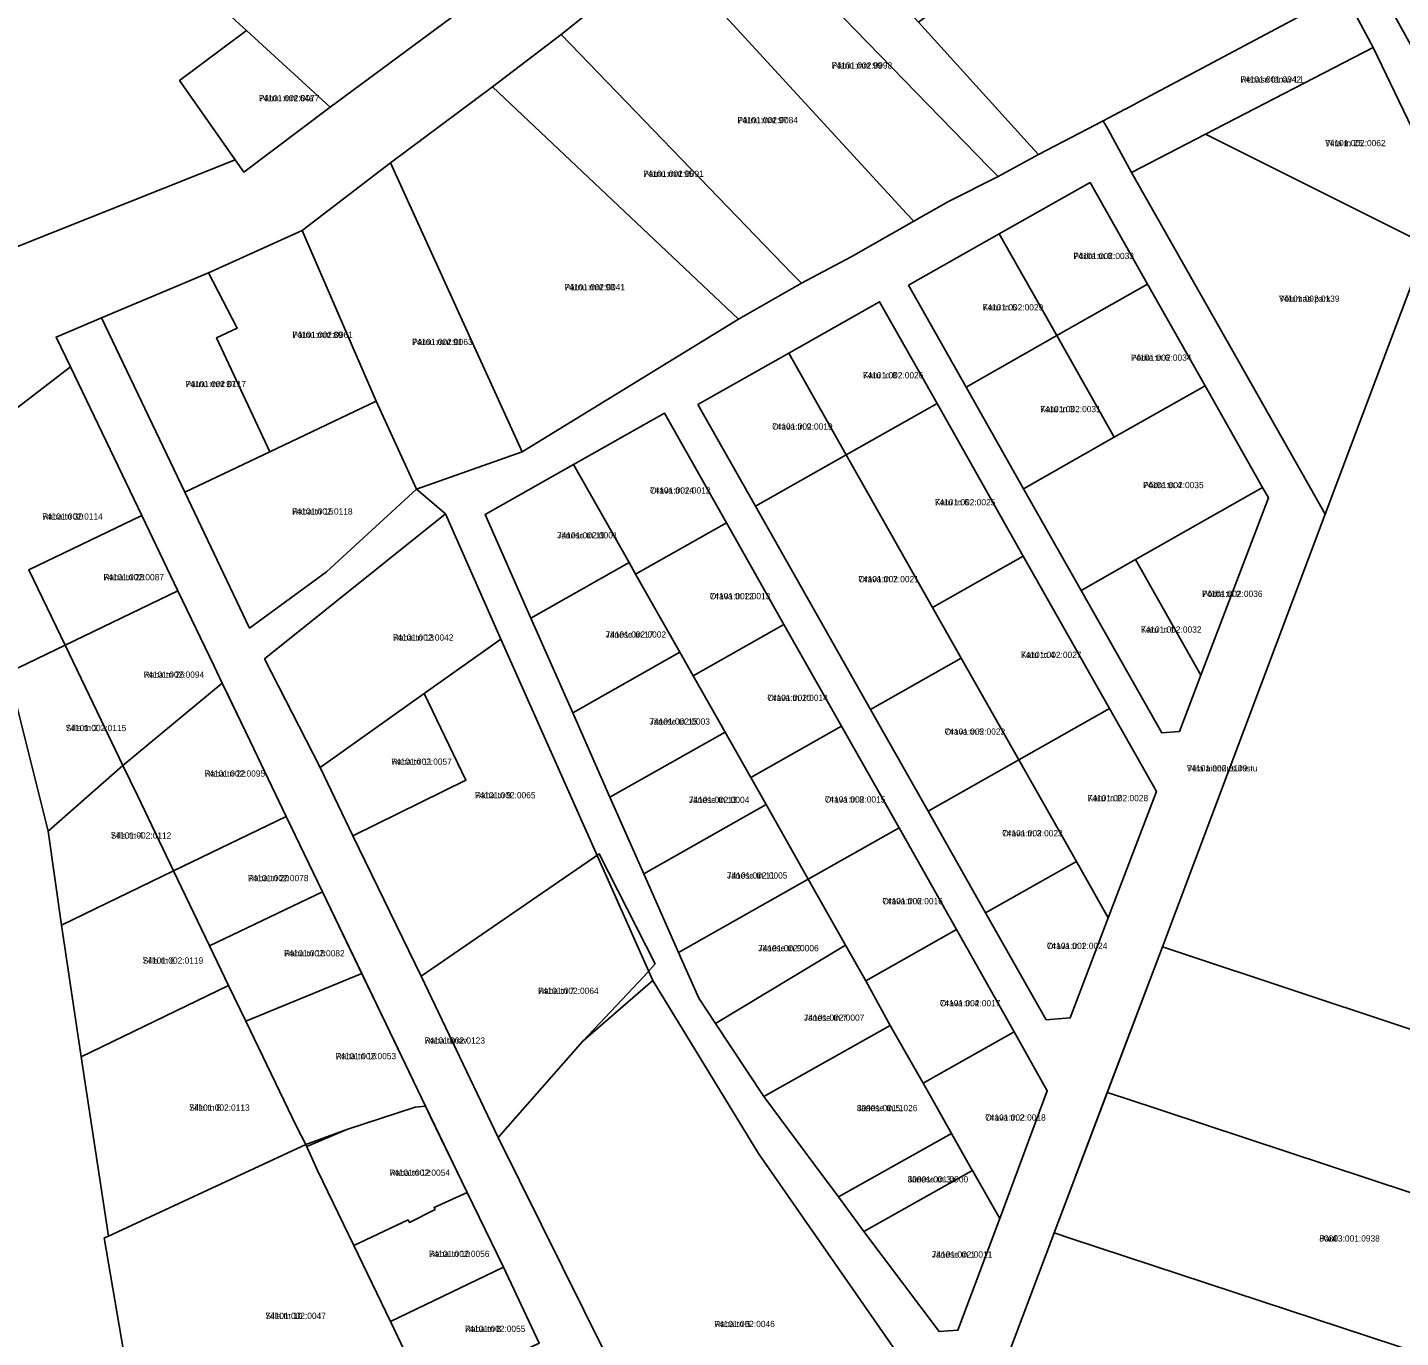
# Model space of a CAD drawing. Extents: x 524000 to 564260, y 6469338 to 6496391.
# Drawn here: x 539303.8 to 539632.9, y 6474807.9 to 6475121.9 of the extents above; entities that cross this region are included whole.
import ezdxf

# ---------------------------------------------------------------- set-up
doc = ezdxf.new("R2010")
doc.units = 0
for name, color, linetype in [('L_AADRESS', 7, 'Continuous'), ('PIIR', 7, 'Continuous'), ('TUNNUS', 7, 'Continuous')]:
    doc.layers.add(name, color=color, linetype=linetype)

msp = doc.modelspace()

# ---------------------------------------------------------------- linework, layer by layer
at = {"layer": 'PIIR'}
for points in [[(539295.23, 6475337.55), (539350.69, 6475352.27), (539371.64, 6475348.56), (539404.12, 6475358.99), (539449.99, 6475367.58), (539454.72, 6475343.6), (539447.84, 6475341.41), (539440.94, 6475342.71), (539417.67, 6475333.57), (539446.06, 6475253.45), (539454.39, 6475235.4), (539416.27, 6475208.15), (539414.96, 6475204.32), (539400.63, 6475162.15), (539381.45, 6475172.98), (539379.48, 6475174.52), (539352.83, 6475124.35), (539356.29, 6475121.18), (539340.27, 6475109.17), (539353.64, 6475090.16), (539301.46, 6475069.45)], [(539456.7, 6475140.24), (539431.73, 6475120.22), (539415.28, 6475107.69), (539390.84, 6475089.49), (539369.67, 6475073.29), (539347.22, 6475063.12), (539321.55, 6475052.32), (539310.68, 6475047.72), (539314.11, 6475040.57), (539281.27, 6475015.31)], [(539301.46, 6475069.45), (539353.64, 6475090.16), (539355.68, 6475087.26), (539376.38, 6475102.78), (539412.45, 6475129.6)], [(539426.49, 6474806.62), (539417.93, 6474824.8), (539409.17, 6474842.68), (539399.21, 6474863.41), (539395.31, 6474871.52), (539391.85, 6474878.73), (539383.19, 6474896.76), (539374.53, 6474914.79), (539365.87, 6474932.81), (539357.21, 6474950.83), (539351.15, 6474963.45), (539350.5, 6474964.8), (539348.55, 6474968.86), (539339.89, 6474986.89), (539331.23, 6475004.92), (539314.11, 6475040.57), (539310.68, 6475047.72), (539321.55, 6475052.32), (539341.52, 6475010.53), (539357.08, 6474977.98), (539375.46, 6474991.41), (539397.03, 6475011.25), (539403.99, 6475005.38), (539360.64, 6474970.59), (539373.97, 6474944.52), (539381.83, 6474928.14), (539398.18, 6474894.53), (539416.64, 6474855.92), (539473.23, 6474741.88)]]:
    msp.add_lwpolyline(points, dxfattribs=at)
for points in [[(539605.37, 6475156.48), (539549.38, 6475215.78), (539554.03, 6475218.82), (539561.15, 6475210.35), (539597.66, 6475177.19), (539603.22, 6475172.2), (539612.5, 6475163.41), (539621.61, 6475144.62), (539625.52, 6475135.5), (539642.98, 6475104.01), (539647.08, 6475099.52), (539649.32, 6475097.06), (539649.25, 6475096.88), (539643.46, 6475081.48), (539641.9, 6475084.73), (539626.35, 6475117.08), (539619.33, 6475130.28)], [(539411.99, 6475130.54), (539412.45, 6475129.6), (539376.38, 6475102.78), (539356.29, 6475121.18), (539352.83, 6475124.35), (539379.48, 6475174.52), (539381.45, 6475172.98), (539400.63, 6475162.15), (539403.34, 6475160.78)], [(539546.15, 6475091.47), (539544.25, 6475093.57), (539517.4, 6475123.15), (539538.81, 6475138.94), (539539.57, 6475139.5), (539534.11, 6475145.91), (539565.08, 6475172.46), (539591.7, 6475144.75), (539605.37, 6475156.48), (539619.33, 6475130.28), (539571.71, 6475104.85), (539566.99, 6475102.33), (539566.92, 6475102.34), (539561.62, 6475099.53)], [(539474.41, 6475135.12), (539464.3, 6475146.34), (539462.39, 6475148.47), (539481.3, 6475162.97), (539517.4, 6475123.15), (539544.25, 6475093.57), (539546.15, 6475091.47), (539536.43, 6475086.16), (539534.11, 6475088.54), (539482.15, 6475142.07)], [(539514.52, 6475077.34), (539456.7, 6475140.24), (539464.3, 6475146.34), (539474.41, 6475135.12), (539482.15, 6475142.07), (539534.11, 6475088.54), (539536.43, 6475086.16), (539524.57, 6475080.22), (539516.23, 6475075.48)], [(539456.7, 6475140.24), (539514.52, 6475077.34), (539516.23, 6475075.48), (539501.22, 6475066.95), (539489.3, 6475060.62), (539487.12, 6475062.89), (539431.73, 6475120.22)], [(539566.99, 6475102.33), (539571.71, 6475104.85), (539619.33, 6475130.28), (539626.35, 6475117.08), (539586.17, 6475096.34), (539568.44, 6475087.13), (539562.88, 6475097.3), (539561.62, 6475099.53), (539566.92, 6475102.34)], [(539355.68, 6475087.26), (539340.27, 6475109.17), (539356.29, 6475121.18), (539376.38, 6475102.78)], [(539474.22, 6475052), (539415.28, 6475107.69), (539431.73, 6475120.22), (539487.12, 6475062.89), (539489.3, 6475060.62)], [(539586.17, 6475096.34), (539626.35, 6475117.08), (539641.9, 6475084.73), (539643.46, 6475081.48), (539639.08, 6475069.84), (539637.08, 6475070.84)], [(539422.37, 6475020.22), (539390.84, 6475089.49), (539415.28, 6475107.69), (539474.22, 6475052)], [(539546.15, 6475091.47), (539561.62, 6475099.53), (539562.88, 6475097.3), (539568.44, 6475087.13), (539610.58, 6475012.76), (539614.81, 6475005.29), (539575.81, 6474901.59), (539549.89, 6474833.01), (539549.8, 6474832.79), (539532.8, 6474787.68), (539526.92, 6474790.08), (539520.24, 6474792.81), (539479.01, 6474852.03), (539453.69, 6474893.5), (539417.25, 6474975.31), (539403.99, 6475005.38), (539397.03, 6475011.25), (539422.37, 6475020.22), (539474.22, 6475052), (539489.3, 6475060.62), (539501.22, 6475066.95), (539516.23, 6475075.48), (539524.57, 6475080.22), (539536.43, 6475086.16)], [(539568.44, 6475087.13), (539586.17, 6475096.34), (539637.08, 6475070.84), (539639.08, 6475069.84), (539614.81, 6475005.29), (539610.58, 6475012.76)], [(539649.25, 6475096.88), (539656.29, 6475089.89), (539687.76, 6475058.65), (539763.32, 6474839.28), (539580.15, 6474900.15), (539575.81, 6474901.59), (539614.81, 6475005.29), (539639.08, 6475069.84), (539643.46, 6475081.48)], [(539387.43, 6475032.37), (539369.67, 6475073.29), (539390.84, 6475089.49), (539422.37, 6475020.22), (539397.03, 6475011.25)], [(539558.49, 6475084.74), (539536.73, 6475072.43), (539514.99, 6475060.11), (539528.77, 6475035.74), (539542.55, 6475011.37), (539556.34, 6474987), (539575.67, 6474952.84), (539579.88, 6474953.21), (539585.04, 6474966.72), (539601.25, 6475009.16), (539599.85, 6475011.63), (539586.06, 6475036), (539572.27, 6475060.37)], [(539536.73, 6475072.43), (539558.49, 6475084.74), (539572.27, 6475060.37), (539550.52, 6475048.06)], [(539354.06, 6475049.84), (539347.22, 6475063.12), (539369.67, 6475073.29), (539387.43, 6475032.37), (539361.88, 6475020.21), (539349.16, 6475047.56)], [(539514.99, 6475060.11), (539536.73, 6475072.43), (539550.52, 6475048.06), (539528.77, 6475035.74)], [(539321.55, 6475052.32), (539347.22, 6475063.12), (539354.06, 6475049.84), (539349.16, 6475047.56), (539361.88, 6475020.21), (539341.52, 6475010.53)], [(539572.27, 6475060.37), (539586.06, 6475036), (539564.3, 6475023.69), (539550.52, 6475048.06)], [(539508.03, 6475056.17), (539486.27, 6475043.85), (539464.51, 6475031.54), (539478.3, 6475007.17), (539505.87, 6474958.43), (539519.66, 6474934.06), (539533.45, 6474909.69), (539547.93, 6474884.1), (539553.68, 6474884.53), (539562.83, 6474908.52), (539574.4, 6474938.83), (539563.16, 6474958.7), (539542.49, 6474995.24), (539521.81, 6475031.8)], [(539486.27, 6475043.85), (539508.03, 6475056.17), (539521.81, 6475031.8), (539500.06, 6475019.48)], [(539528.77, 6475035.74), (539550.52, 6475048.06), (539564.3, 6475023.69), (539542.55, 6475011.37)], [(539500.06, 6475019.48), (539478.3, 6475007.17), (539464.51, 6475031.54), (539486.27, 6475043.85)], [(539331.23, 6475004.92), (539304.19, 6474991.93), (539312.85, 6474973.9), (539299.32, 6474967.34), (539281.27, 6475015.31), (539314.11, 6475040.57)], [(539542.55, 6475011.37), (539564.3, 6475023.69), (539586.06, 6475036), (539599.85, 6475011.63), (539569.39, 6474994.39), (539556.34, 6474987)], [(539357.08, 6474977.98), (539341.52, 6475010.53), (539361.88, 6475020.21), (539387.43, 6475032.37), (539397.03, 6475011.25), (539375.46, 6474991.41)], [(539521.81, 6475031.8), (539542.49, 6474995.24), (539520.73, 6474982.93), (539500.06, 6475019.48)], [(539456.47, 6475029.51), (539434.71, 6475017.2), (539413.51, 6475005.2), (539424.47, 6474980.38), (539434.51, 6474957.65), (539443.43, 6474937.45), (539451.55, 6474919.06), (539459.88, 6474900.22), (539464.71, 6474889.28), (539468.75, 6474883.21), (539480.33, 6474865.74), (539492.31, 6474849.56), (539498.17, 6474841.65), (539504.3, 6474833.37), (539522.31, 6474809.38), (539526.79, 6474809.7), (539536.83, 6474836.45), (539548.24, 6474867.04), (539540.27, 6474881.19), (539526.48, 6474905.75), (539512.7, 6474930.12), (539498.91, 6474954.49), (539485.13, 6474978.85), (539471.34, 6475003.22)], [(539448, 6474993.7), (539434.71, 6475017.2), (539456.47, 6475029.51), (539471.34, 6475003.22), (539449.58, 6474990.91)], [(539500.06, 6475019.48), (539520.73, 6474982.93), (539527.63, 6474970.75), (539505.87, 6474958.43), (539478.3, 6475007.17)], [(539259.08, 6474994.7), (539281.27, 6475015.31), (539299.32, 6474967.34), (539308.8, 6474929.26), (539311.96, 6474906.78), (539316.72, 6474875.25), (539323.28, 6474832.27), (539322.24, 6474831.82), (539334.08, 6474762.25), (539342.33, 6474726.21), (539350.68, 6474689.75), (539369.7, 6474657.04), (539371.99, 6474653.09), (539338.84, 6474630.7), (539315, 6474716.9), (539304.47, 6474785.89), (539300.16, 6474795.58), (539281.58, 6474922.49), (539272.59, 6474958.92)], [(539413.51, 6475005.2), (539434.71, 6475017.2), (539448, 6474993.7), (539424.47, 6474980.38)], [(539599.85, 6475011.63), (539601.25, 6475009.16), (539585.04, 6474966.72), (539569.39, 6474994.39)], [(539304.19, 6474991.93), (539331.23, 6475004.92), (539339.89, 6474986.89), (539312.85, 6474973.9)], [(539360.64, 6474970.59), (539403.99, 6475005.38), (539417.25, 6474975.31), (539398.92, 6474962.27), (539373.97, 6474944.52)], [(539460.18, 6474972.18), (539449.58, 6474990.91), (539471.34, 6475003.22), (539485.13, 6474978.85), (539463.37, 6474966.54)], [(539520.73, 6474982.93), (539542.49, 6474995.24), (539563.16, 6474958.7), (539541.41, 6474946.38), (539527.63, 6474970.75)], [(539569.39, 6474994.39), (539585.04, 6474966.72), (539579.88, 6474953.21), (539575.67, 6474952.84), (539556.34, 6474987)], [(539424.47, 6474980.38), (539448, 6474993.7), (539449.58, 6474990.91), (539460.18, 6474972.18), (539434.51, 6474957.65)], [(539325.83, 6474946.86), (539321.51, 6474955.87), (539312.85, 6474973.9), (539339.89, 6474986.89), (539348.55, 6474968.86), (539350.5, 6474964.8), (539326.7, 6474945.06)], [(539471, 6474953.06), (539463.37, 6474966.54), (539485.13, 6474978.85), (539498.91, 6474954.49), (539477.16, 6474942.18)], [(539381.83, 6474928.14), (539408.9, 6474941.5), (539398.92, 6474962.27), (539415.06, 6474973.75), (539417.25, 6474975.31), (539440.34, 6474923.48), (539437.97, 6474921.84), (539398.18, 6474894.53)], [(539299.32, 6474967.34), (539312.85, 6474973.9), (539321.51, 6474955.87), (539325.83, 6474946.86), (539326.7, 6474945.06), (539308.8, 6474929.26)], [(539434.51, 6474957.65), (539460.18, 6474972.18), (539463.37, 6474966.54), (539471, 6474953.06), (539443.43, 6474937.45)], [(539505.87, 6474958.43), (539527.63, 6474970.75), (539541.41, 6474946.38), (539519.66, 6474934.06)], [(539330.17, 6474937.85), (539326.7, 6474945.06), (539350.5, 6474964.8), (539357.21, 6474950.83), (539365.87, 6474932.81), (539338.83, 6474919.82)], [(539373.97, 6474944.52), (539398.92, 6474962.27), (539408.9, 6474941.5), (539381.83, 6474928.14)], [(539541.41, 6474946.38), (539563.16, 6474958.7), (539574.4, 6474938.83), (539562.83, 6474908.52), (539555.2, 6474922.01)], [(539443.43, 6474937.45), (539471, 6474953.06), (539477.16, 6474942.18), (539480.85, 6474935.65), (539451.55, 6474919.06)], [(539480.85, 6474935.65), (539477.16, 6474942.18), (539498.91, 6474954.49), (539512.7, 6474930.12), (539490.94, 6474917.81)], [(539308.8, 6474929.26), (539326.7, 6474945.06), (539330.17, 6474937.85), (539338.83, 6474919.82), (539311.96, 6474906.78)], [(539519.66, 6474934.06), (539541.41, 6474946.38), (539555.2, 6474922.01), (539533.45, 6474909.69)], [(539451.55, 6474919.06), (539480.85, 6474935.65), (539490.94, 6474917.81), (539459.88, 6474900.22)], [(539338.83, 6474919.82), (539365.87, 6474932.81), (539374.53, 6474914.79), (539347.49, 6474901.8)], [(539499.9, 6474901.96), (539490.94, 6474917.81), (539512.7, 6474930.12), (539526.48, 6474905.75), (539504.73, 6474893.44)], [(539398.18, 6474894.53), (539437.97, 6474921.84), (539440.85, 6474923.83), (539454.25, 6474897.53), (539451.61, 6474894.53), (539436.93, 6474878.98), (539416.64, 6474855.92)], [(539555.2, 6474922.01), (539562.83, 6474908.52), (539553.68, 6474884.53), (539547.93, 6474884.1), (539533.45, 6474909.69)], [(539338.83, 6474919.82), (539347.49, 6474901.8), (539352.04, 6474892.33), (539316.72, 6474875.25), (539311.96, 6474906.78)], [(539464.71, 6474889.28), (539459.88, 6474900.22), (539490.94, 6474917.81), (539499.9, 6474901.96), (539468.75, 6474883.21)], [(539352.04, 6474892.33), (539347.49, 6474901.8), (539374.53, 6474914.79), (539383.93, 6474895.22), (539356.15, 6474883.77)], [(539504.73, 6474893.44), (539526.48, 6474905.75), (539540.27, 6474881.19), (539518.48, 6474868.87), (539510.58, 6474882.73)], [(539468.75, 6474883.21), (539499.9, 6474901.96), (539504.73, 6474893.44), (539510.58, 6474882.73), (539480.33, 6474865.74)], [(539562.61, 6474866.67), (539575.81, 6474901.59), (539580.15, 6474900.15), (539763.32, 6474839.28), (539713.71, 6474816.76), (539566.31, 6474865.45)], [(539316.72, 6474875.25), (539352.04, 6474892.33), (539356.15, 6474883.77), (539368.27, 6474858.53), (539370.57, 6474854.18), (539323.28, 6474832.27)], [(539370.57, 6474854.18), (539368.27, 6474858.53), (539356.15, 6474883.77), (539383.93, 6474895.22), (539399.21, 6474863.41), (539396.74, 6474863.12), (539380.33, 6474857.77), (539370.78, 6474853.71)], [(539416.64, 6474855.92), (539436.93, 6474878.98), (539453.69, 6474893.5), (539479.01, 6474852.03), (539520.24, 6474792.81), (539505.23, 6474762.64), (539473.23, 6474741.88)], [(539492.31, 6474849.56), (539480.33, 6474865.74), (539510.58, 6474882.73), (539518.48, 6474868.87), (539520.46, 6474865.38), (539525.29, 6474856.85), (539498.17, 6474841.65)], [(539518.48, 6474868.87), (539540.27, 6474881.19), (539548.24, 6474867.04), (539536.83, 6474836.45), (539530.71, 6474847.27), (539530.31, 6474847.97), (539530.02, 6474848.48), (539525.29, 6474856.85), (539520.46, 6474865.38)], [(539553.84, 6474831.7), (539549.89, 6474833.01), (539562.61, 6474866.67), (539566.31, 6474865.45), (539713.71, 6474816.76), (539664.49, 6474795.23)], [(539373.32, 6474847.99), (539370.57, 6474854.18), (539380.33, 6474857.77), (539396.74, 6474863.12), (539399.21, 6474863.41), (539400.44, 6474860.8), (539409.17, 6474842.68), (539401.28, 6474839.08), (539401.5, 6474838.64), (539395.39, 6474835.49), (539395.05, 6474836.14), (539382.03, 6474829.99)], [(539530.31, 6474847.97), (539529.46, 6474847.49), (539504.3, 6474833.37), (539498.17, 6474841.65), (539525.29, 6474856.85), (539530.02, 6474848.48)], [(539322.24, 6474831.82), (539323.28, 6474832.27), (539370.57, 6474854.18), (539373.32, 6474847.99), (539382.03, 6474829.99), (539390.85, 6474811.81), (539399.45, 6474793.76), (539373.04, 6474780.97), (539334.08, 6474762.25)], [(539504.3, 6474833.37), (539529.46, 6474847.49), (539530.31, 6474847.97), (539530.71, 6474847.27), (539536.83, 6474836.45), (539526.79, 6474809.7), (539522.31, 6474809.38)], [(539382.03, 6474829.99), (539395.05, 6474836.14), (539395.39, 6474835.49), (539401.5, 6474838.64), (539401.28, 6474839.08), (539409.17, 6474842.68), (539417.93, 6474824.8), (539390.85, 6474811.81)], [(539521.46, 6474757.86), (539532.79, 6474787.65), (539532.8, 6474787.68), (539549.8, 6474832.79), (539549.89, 6474833.01), (539553.84, 6474831.7), (539664.49, 6474795.23), (539509.43, 6474726.09), (539509.63, 6474726.6), (539518.32, 6474749.31), (539519.71, 6474753.1)], [(539390.85, 6474811.81), (539417.93, 6474824.8), (539426.49, 6474806.62), (539399.45, 6474793.76)]]:
    msp.add_lwpolyline(points, close=True, dxfattribs=at)

# ---------------------------------------------------------------- texts
at = {"layer": 'L_AADRESS'}
for s, p in [('Pärnu mnt 99', (539496.57, 6475112.05)), ('Rebase tänav L1', (539594.53, 6475108.71)), ('Pärnu mnt 64a', (539359.28, 6475104.22)), ('Pärnu mnt 97', (539473.98, 6475098.97)), ('Viira tn 25', (539614.81, 6475093.46)), ('Pärnu mnt 95', (539451.4, 6475086.11)), ('Põdra tn 8', (539554.5, 6475066.4)), ('Pärnu mnt 93', (539432.53, 6475058.92)), ('Võlumaa park', (539603.76, 6475056.16)), ('Karu tn 5', (539532.76, 6475054.09)), ('Pärnu mnt 89', (539367.32, 6475047.51)), ('Pärnu mnt 91', (539396.02, 6475045.79)), ('Põdra tn 6', (539568.29, 6475042.03)), ('Pärnu mnt 87', (539341.71, 6475035.71)), ('Karu tn 8', (539504.04, 6475037.82)), ('Karu tn 3', (539546.54, 6475029.71)), ('Orava tn 9', (539482.29, 6475025.51)), ('Orava tn 14', (539453.03, 6475010.21)), ('Põdra tn 4', (539571.2, 6475011.5)), ('Karu tn 6', (539521.28, 6475007.37)), ('Raba tn 30', (539307.38, 6475003.96)), ('Raba tn 15', (539367.25, 6475005.18)), ('Jänese tn 19', (539430.75, 6474999.45)), ('Raba tn 28', (539322.04, 6474989.41)), ('Orava tn 7', (539502.96, 6474988.95)), ('Orava tn 12', (539467.36, 6474984.88)), ('Põdra tn 2', (539585.32, 6474985.43)), ('Karu tn 1', (539570.69, 6474976.87)), ('Raba tn 13', (539391.41, 6474974.95)), ('Jänese tn 17', (539442.38, 6474975.67)), ('Karu tn 4', (539541.94, 6474970.81)), ('Raba tn 26', (539331.68, 6474966.06)), ('Orava tn 10', (539481.14, 6474960.51)), ('Silla tn 2', (539313.01, 6474953.27)), ('Jänese tn 15', (539452.88, 6474954.82)), ('Orava tn 5', (539523.64, 6474952.4)), ('Raba tn 11', (539391.03, 6474945.21)), ('Viira aiandusühistu', (539581.66, 6474943.61)), ('Raba tn 22', (539346.29, 6474942.35)), ('Raba tn 9', (539411.09, 6474937.16)), ('Jänese tn 13', (539462.33, 6474936.06)), ('Orava tn 8', (539494.93, 6474936.15)), ('Karu tn 2', (539557.9, 6474936.48)), ('Silla tn 4', (539323.81, 6474927.52)), ('Orava tn 3', (539537.43, 6474928.04)), ('Raba tn 20', (539356.68, 6474917.3)), ('Jänese tn 11', (539471.46, 6474917.93)), ('Orava tn 6', (539508.71, 6474911.78)), ('Orava tn 1', (539548.14, 6474901.06)), ('Silla tn 6', (539331.45, 6474897.54)), ('Raba tn 18', (539365.34, 6474899.28)), ('Jänese tn 9', (539478.94, 6474900.51)), ('Raba tn 7', (539426.21, 6474890.29)), ('Orava tn 4', (539522.5, 6474887.32)), ('Jänese tn 7', (539489.89, 6474883.85)), ('Raba tänav', (539398.98, 6474878.38)), ('Raba tn 16', (539377.68, 6474874.64)), ('Silla tn 8', (539342.58, 6474862.3)), ('Jänese tn 5', (539502.61, 6474862.19)), ('Orava tn 2', (539533.36, 6474859.93)), ('Raba tn 12', (539390.59, 6474846.7)), ('Jänese tn 3a', (539514.78, 6474845.11)), ('Pauli', (539613.43, 6474830.95)), ('Raba tn 10', (539400.05, 6474827.24)), ('Jänese tn 1', (539520.56, 6474827.1)), ('Silla tn 10', (539360.85, 6474812.39)), ('Raba tn 8', (539408.65, 6474809.28)), ('Raba tn 5', (539468.44, 6474810.44))]:
    msp.add_text(s, height=1.5, dxfattribs=at).set_placement(p)
at = {"layer": 'TUNNUS'}
for s, p in [('74101:002:0098', (539496.57, 6475112.05)), ('74101:001:0342', (539594.53, 6475108.71)), ('74101:002:0077', (539359.28, 6475104.22)), ('74101:002:0084', (539473.98, 6475098.97)), ('74101:002:0062', (539614.81, 6475093.46)), ('74101:002:0091', (539451.4, 6475086.11)), ('74101:002:0033', (539554.5, 6475066.4)), ('74101:002:0041', (539432.53, 6475058.92)), ('74101:002:0139', (539603.76, 6475056.16)), ('74101:002:0029', (539532.76, 6475054.09)), ('74101:002:0061', (539367.32, 6475047.51)), ('74101:002:0063', (539396.02, 6475045.79)), ('74101:002:0034', (539568.29, 6475042.03)), ('74101:002:0117', (539341.71, 6475035.71)), ('74101:002:0026', (539504.04, 6475037.82)), ('74101:002:0031', (539546.54, 6475029.71)), ('74101:002:0019', (539482.29, 6475025.51)), ('74101:002:0012', (539453.03, 6475010.21)), ('74101:002:0035', (539571.2, 6475011.5)), ('74101:002:0025', (539521.28, 6475007.37)), ('74101:002:0114', (539307.38, 6475003.96)), ('74101:002:0118', (539367.25, 6475005.18)), ('74101:002:0001', (539430.75, 6474999.45)), ('74101:002:0087', (539322.04, 6474989.41)), ('74101:002:0021', (539502.96, 6474988.95)), ('74101:002:0013', (539467.36, 6474984.88)), ('74101:002:0036', (539585.32, 6474985.43)), ('74101:002:0032', (539570.69, 6474976.87)), ('74101:002:0042', (539391.41, 6474974.95)), ('74101:002:0002', (539442.38, 6474975.67)), ('74101:002:0027', (539541.94, 6474970.81)), ('74101:002:0094', (539331.68, 6474966.06)), ('74101:002:0014', (539481.14, 6474960.51)), ('74101:002:0003', (539452.88, 6474954.82)), ('74101:002:0115', (539313.01, 6474953.27)), ('74101:002:0022', (539523.64, 6474952.4)), ('74101:002:0057', (539391.03, 6474945.21)), ('74101:002:0109', (539581.66, 6474943.61)), ('74101:002:0095', (539346.29, 6474942.35)), ('74101:002:0065', (539411.09, 6474937.16)), ('74101:002:0004', (539462.33, 6474936.06)), ('74101:002:0015', (539494.93, 6474936.15)), ('74101:002:0028', (539557.9, 6474936.48)), ('74101:002:0112', (539323.81, 6474927.52)), ('74101:002:0023', (539537.43, 6474928.04)), ('74101:002:0078', (539356.68, 6474917.3)), ('74101:002:0005', (539471.46, 6474917.93)), ('74101:002:0016', (539508.71, 6474911.78)), ('74101:002:0024', (539548.14, 6474901.06)), ('74101:002:0119', (539331.45, 6474897.54)), ('74101:002:0082', (539365.34, 6474899.28)), ('74101:002:0006', (539478.94, 6474900.51)), ('74101:002:0064', (539426.21, 6474890.29)), ('74101:002:0017', (539522.5, 6474887.32)), ('74101:002:0007', (539489.89, 6474883.85)), ('74101:002:0123', (539398.98, 6474878.38)), ('74101:002:0053', (539377.68, 6474874.64)), ('74101:002:0113', (539342.58, 6474862.3)), ('80901:001:1026', (539502.61, 6474862.19)), ('74101:002:0018', (539533.36, 6474859.93)), ('74101:002:0054', (539390.59, 6474846.7)), ('80901:001:0900', (539514.78, 6474845.11)), ('80803:001:0938', (539613.43, 6474830.95)), ('74101:002:0056', (539400.05, 6474827.24)), ('74101:002:0011', (539520.56, 6474827.1)), ('74101:002:0047', (539360.85, 6474812.39)), ('74101:002:0055', (539408.65, 6474809.28)), ('74101:002:0046', (539468.44, 6474810.44))]:
    msp.add_text(s, height=1.5, dxfattribs=at).set_placement(p)

doc.saveas('drawing.dxf')
